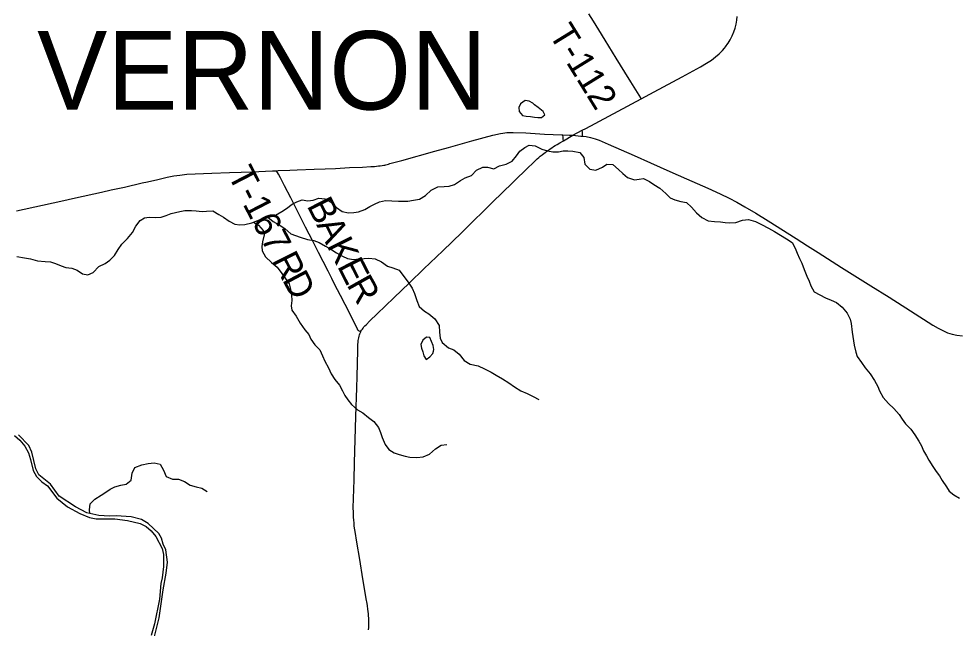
# Model space of a CAD drawing. Extents: x 1442749 to 1756758, y 235267 to 677782.
# Drawn here: x 1557967 to 1568709, y 500562 to 507542 of the extents above; entities that cross this region are included whole.
import ezdxf

# ---------------------------------------------------------------- set-up
doc = ezdxf.new("R2010")
doc.units = 0
for name, color, linetype in [('GM_X_Major_River', 7, 'Continuous'), ('GM_X_Minor_Lake', 7, 'Continuous'), ('GM_X_Minor_River', 7, 'Continuous'), ('GM_X_State_Route', 7, 'Continuous'), ('GM_X_Township_Road', 7, 'Continuous'), ('GM_X_Township_Road_Text', 7, 'Continuous'), ('GM_X_Township_Text', 7, 'Continuous')]:
    doc.layers.add(name, color=color, linetype=linetype)

msp = doc.modelspace()

# ---------------------------------------------------------------- linework, layer by layer
at = {"layer": 'GM_X_Major_River'}
for points in [[(1557917, 502769), (1557981, 502714), (1558036, 502647), (1558079, 502570), (1558103, 502496), (1558132, 502367), (1558171, 502300), (1558230, 502240), (1558297, 502191), (1558403, 502051), (1558524, 501951), (1558667, 501875), (1558778, 501829), (1558854, 501814), (1559065, 501813), (1559210, 501795), (1559356, 501761), (1559424, 501726), (1559483, 501677), (1559538, 501612), (1559610, 501475), (1559625, 501405), (1559625, 501267), (1559609, 501140), (1559592, 501075), (1559578, 500896), (1559522, 500611), (1559484, 500477)], [(1559505, 500406), (1559573, 500680), (1559619, 501000), (1559656, 501194), (1559668, 501320), (1559652, 501459), (1559621, 501525), (1559602, 501594), (1559571, 501648), (1559448, 501762), (1559371, 501807), (1559253, 501839), (1559081, 501851), (1559005, 501844), (1558885, 501854), (1558780, 501876), (1558745, 501884), (1558618, 501954), (1558430, 502074), (1558330, 502210), (1558195, 502318), (1558162, 502389), (1558117, 502578), (1558082, 502654), (1557965, 502776)]]:
    msp.add_lwpolyline(points, dxfattribs=at)
at = {"layer": 'GM_X_Minor_Lake'}
for points in [[(1563853, 506574), (1563808, 506599), (1563762, 506606), (1563711, 506569), (1563692, 506527), (1563695, 506479), (1563734, 506436), (1563776, 506426), (1563826, 506423), (1563870, 506416), (1563910, 506411), (1563929, 506411)], [(1563929, 506411), (1563952, 506410), (1563989, 506442), (1563969, 506482), (1563914, 506527), (1563869, 506556), (1563853, 506574)], [(1562592, 503862), (1562571, 503813), (1562579, 503770), (1562594, 503728), (1562605, 503680), (1562631, 503641), (1562671, 503669), (1562706, 503710), (1562713, 503734)], [(1562713, 503734), (1562718, 503754), (1562711, 503801), (1562690, 503845), (1562674, 503891), (1562634, 503896), (1562592, 503862)]]:
    msp.add_lwpolyline(points, dxfattribs=at)
at = {"layer": 'GM_X_Minor_River'}
for points in [[(1559408, 505262), (1559460, 505271), (1559532, 505267), (1559598, 505270), (1559654, 505289), (1559711, 505310), (1559811, 505336), (1559867, 505347), (1559945, 505345), (1559997, 505344), (1560067, 505335), (1560117, 505338), (1560189, 505342), (1560257, 505301), (1560310, 505268), (1560377, 505224), (1560440, 505191), (1560496, 505182), (1560554, 505185), (1560635, 505205), (1560705, 505232), (1560778, 505261), (1560905, 505294), (1560977, 505335), (1561032, 505370), (1561097, 505419), (1561152, 505446), (1561210, 505467), (1561276, 505457), (1561336, 505464), (1561403, 505489), (1561471, 505481), (1561540, 505440), (1561604, 505379), (1561670, 505335), (1561741, 505320), (1561803, 505323), (1561857, 505330), (1561930, 505358), (1561987, 505391), (1562039, 505418), (1562096, 505447), (1562164, 505462), (1562238, 505458), (1562312, 505453), (1562420, 505455), (1562486, 505465), (1562555, 505476), (1562621, 505519), (1562689, 505580), (1562765, 505618), (1562836, 505623), (1562894, 505624), (1562956, 505645), (1563025, 505689), (1563078, 505720), (1563150, 505747), (1563207, 505808), (1563280, 505842), (1563332, 505843), (1563404, 505822), (1563469, 505859), (1563545, 505877), (1563616, 505912), (1563665, 505973), (1563704, 506026), (1563759, 506069), (1563809, 506096), (1563879, 506085), (1563954, 506048), (1564018, 506028), (1564080, 506019), (1564144, 506020), (1564200, 506029), (1564252, 506028), (1564310, 506025), (1564390, 506009), (1564437, 505952), (1564447, 505878), (1564504, 505820), (1564574, 505807), (1564648, 505842), (1564699, 505877), (1564767, 505873), (1564832, 505814), (1564883, 505771), (1564934, 505726), (1565017, 505698), (1565068, 505707), (1565120, 505712), (1565187, 505679), (1565238, 505644), (1565304, 505602), (1565374, 505541), (1565425, 505490), (1565477, 505467), (1565546, 505451), (1565612, 505436), (1565667, 505385), (1565724, 505318), (1565787, 505266)], [(1557944, 504818), (1558034, 504806), (1558102, 504793), (1558183, 504771), (1558271, 504761), (1558331, 504758), (1558387, 504741), (1558452, 504712), (1558506, 504694), (1558574, 504687), (1558635, 504664), (1558698, 504621), (1558756, 504611), (1558817, 504638), (1558882, 504705), (1558955, 504740), (1559008, 504779), (1559063, 504832), (1559104, 504901), (1559147, 504962), (1559211, 505027), (1559270, 505096), (1559306, 505167), (1559357, 505231), (1559408, 505262)], [(1560654, 505213), (1560710, 505180), (1560765, 505119), (1560776, 505066), (1560758, 504987), (1560751, 504935), (1560754, 504885), (1560793, 504814), (1560859, 504750), (1560926, 504699), (1560977, 504624), (1561018, 504573), (1561064, 504508), (1561079, 504447), (1561090, 504377), (1561092, 504315), (1561085, 504255), (1561094, 504203), (1561141, 504136), (1561189, 504054)], [(1560819, 505271), (1560879, 505219), (1560946, 505183), (1561013, 505140), (1561082, 505080), (1561189, 505042), (1561273, 505015), (1561343, 505001), (1561406, 504978), (1561477, 504938), (1561539, 504905), (1561606, 504862), (1561673, 504822), (1561730, 504795), (1561800, 504784), (1561868, 504793), (1561921, 504798), (1561975, 504800), (1562048, 504791), (1562118, 504758), (1562189, 504710), (1562248, 504691), (1562320, 504663), (1562376, 504592), (1562423, 504525), (1562472, 504458), (1562496, 504394), (1562523, 504317), (1562551, 504248), (1562610, 504193), (1562662, 504162), (1562730, 504106), (1562778, 504029)], [(1565787, 505266), (1565860, 505229), (1565932, 505219), (1565998, 505216), (1566052, 505209), (1566107, 505204), (1566176, 505208), (1566250, 505237), (1566322, 505244), (1566400, 505222), (1566469, 505185), (1566548, 505143), (1566618, 505106), (1566687, 505062), (1566756, 505021), (1566819, 504979), (1566854, 504915), (1566877, 504858), (1566903, 504795), (1566930, 504743), (1566957, 504672), (1566989, 504595), (1567014, 504537), (1567035, 504482), (1567073, 504415), (1567135, 504382), (1567200, 504347), (1567268, 504321), (1567327, 504292), (1567392, 504239), (1567449, 504172), (1567485, 504103), (1567494, 504051), (1567506, 503954)], [(1561189, 504054), (1561240, 503981), (1561289, 503926), (1561309, 503874), (1561356, 503809), (1561413, 503750), (1561442, 503681), (1561471, 503619), (1561512, 503544), (1561545, 503474), (1561586, 503411), (1561639, 503344), (1561674, 503279), (1561700, 503229), (1561735, 503176), (1561774, 503126), (1561843, 503063), (1561905, 503028), (1561970, 502977), (1562030, 502930), (1562085, 502861), (1562106, 502803), (1562127, 502746), (1562160, 502666), (1562203, 502609), (1562265, 502570), (1562323, 502551), (1562392, 502532), (1562444, 502523), (1562522, 502518), (1562596, 502525), (1562669, 502556), (1562736, 502616), (1562801, 502657), (1562869, 502666)], [(1562778, 504029), (1562783, 503952), (1562790, 503884), (1562812, 503833), (1562885, 503772), (1562947, 503749), (1563010, 503700), (1563067, 503629), (1563136, 503588), (1563224, 503569), (1563298, 503532), (1563375, 503493), (1563433, 503460), (1563504, 503417), (1563576, 503372), (1563643, 503327), (1563715, 503282), (1563786, 503249), (1563856, 503216), (1563919, 503183)], [(1567506, 503954), (1567521, 503854), (1567530, 503803), (1567547, 503725), (1567564, 503675), (1567615, 503604), (1567656, 503545), (1567711, 503474), (1567764, 503401), (1567799, 503331), (1567819, 503280), (1567862, 503204), (1567923, 503135), (1567982, 503078), (1568043, 503009), (1568078, 502958), (1568117, 502901), (1568177, 502840), (1568226, 502778), (1568269, 502703), (1568300, 502650), (1568323, 502592), (1568356, 502535), (1568386, 502485), (1568431, 502414), (1568470, 502357), (1568505, 502307), (1568536, 502252), (1568585, 502181), (1568619, 502131), (1568670, 502090), (1568734, 502051)], [(1558779, 501875), (1558778, 501917), (1558785, 501986), (1558838, 502041), (1558912, 502086), (1558963, 502121), (1559015, 502153), (1559068, 502182), (1559136, 502199), (1559196, 502212), (1559255, 502258), (1559264, 502336), (1559295, 502402), (1559376, 502432), (1559448, 502448), (1559518, 502455), (1559586, 502442), (1559623, 502371), (1559654, 502300), (1559726, 502271), (1559796, 502268), (1559866, 502243), (1559931, 502200), (1559999, 502180), (1560063, 502165), (1560124, 502128)]]:
    msp.add_lwpolyline(points, dxfattribs=at)
at = {"layer": 'GM_X_State_Route'}
for points in [[(1563739, 505781), (1563800, 505841), (1563844, 505882), (1563876, 505913), (1563903, 505937), (1563920, 505953), (1563937, 505967), (1563959, 505985), (1563982, 506003), (1563999, 506015), (1564012, 506025), (1564031, 506039), (1564049, 506052), (1564068, 506064), (1564088, 506078), (1564109, 506091), (1564130, 506104), (1564162, 506122), (1564202, 506145), (1564308, 506208), (1564417, 506265), (1564457, 506286), (1565091, 506626), (1565241, 506706), (1565562, 506878), (1565770, 506991), (1565841, 507033), (1565896, 507069), (1565943, 507105), (1565985, 507142), (1566022, 507180), (1566045, 507207), (1566056, 507220), (1566085, 507260), (1566086, 507261), (1566112, 507302), (1566135, 507346), (1566154, 507392), (1566169, 507436), (1566180, 507481), (1566188, 507526), (1566192, 507569)], [(1557943, 505342), (1558449, 505455), (1558615, 505492), (1558913, 505558), (1559025, 505582), (1559176, 505615), (1559380, 505663), (1559440, 505675), (1559558, 505702), (1559664, 505727), (1559744, 505743), (1559809, 505752), (1559890, 505761), (1559988, 505766), (1560178, 505773), (1560378, 505781), (1560513, 505787), (1560634, 505790), (1560873, 505800), (1560918, 505802), (1560938, 505803), (1561069, 505808), (1561155, 505812), (1561348, 505820), (1561473, 505824), (1561594, 505829), (1561754, 505837), (1561902, 505843), (1561997, 505849), (1562039, 505851), (1562063, 505853), (1562086, 505856), (1562105, 505858), (1562126, 505861), (1562147, 505865), (1562158, 505867), (1562170, 505871), (1562183, 505874), (1562198, 505878), (1562215, 505883), (1562231, 505887), (1562246, 505891), (1562351, 505920), (1562730, 506025), (1562885, 506068), (1563046, 506113), (1563154, 506143), (1563394, 506209), (1563480, 506228), (1563507, 506233), (1563531, 506237), (1563554, 506239), (1563577, 506240), (1563597, 506241), (1563626, 506241), (1563770, 506234), (1563986, 506222), (1564183, 506213), (1564196, 506213), (1564271, 506209), (1564288, 506209), (1564308, 506208)], [(1564202, 506145), (1564200, 506166), (1564198, 506184), (1564196, 506213)], [(1564308, 506208), (1564402, 506199), (1564422, 506196), (1564461, 506192), (1564513, 506181), (1564564, 506168), (1564611, 506151), (1564713, 506107), (1565010, 505975), (1565199, 505891), (1565421, 505793), (1565610, 505709), (1565856, 505601), (1565994, 505539), (1566098, 505489), (1566188, 505442), (1566279, 505390), (1566406, 505314), (1566546, 505229), (1566867, 505024), (1566994, 504943), (1567119, 504864), (1567385, 504695), (1567720, 504483), (1567929, 504352), (1568176, 504196), (1568430, 504034), (1568492, 503997), (1568544, 503970), (1568598, 503947), (1568651, 503931), (1568705, 503919), (1568769, 503909)], [(1564422, 506196), (1564421, 506212), (1564419, 506241), (1564417, 506265)], [(1561971, 500545), (1561973, 500572), (1561975, 500595), (1561976, 500613), (1561976, 500633), (1561975, 500653), (1561974, 500679), (1561972, 500704), (1561970, 500726), (1561967, 500752), (1561963, 500782), (1561958, 500818), (1561954, 500845), (1561945, 500899), (1561936, 500947), (1561906, 501127), (1561870, 501349), (1561837, 501548), (1561818, 501670), (1561812, 501707), (1561808, 501736), (1561805, 501765), (1561801, 501805), (1561799, 501831), (1561798, 501853), (1561797, 501892), (1561796, 501940), (1561805, 502263), (1561812, 502458), (1561827, 502985), (1561835, 503315), (1561840, 503445), (1561847, 503743), (1561849, 503789), (1561850, 503815), (1561851, 503835), (1561854, 503856), (1561856, 503872), (1561858, 503888), (1561863, 503908), (1561867, 503923), (1561871, 503935), (1561877, 503950), (1561881, 503957), (1561883, 503963), (1561891, 503975), (1561900, 503988), (1561908, 503999), (1561918, 504012), (1561929, 504024), (1561942, 504038), (1561984, 504081), (1562068, 504163), (1562260, 504345), (1562440, 504517), (1562605, 504678), (1562820, 504886), (1563037, 505095), (1563181, 505235), (1563277, 505329), (1563376, 505425), (1563521, 505567), (1563603, 505648), (1563687, 505731), (1563739, 505781)]]:
    msp.add_lwpolyline(points, dxfattribs=at)
at = {"layer": 'GM_X_Township_Road'}
for points in [[(1565091, 506626), (1565086, 506635), (1564974, 506819), (1564905, 506931), (1564807, 507090), (1564678, 507296), (1564608, 507414), (1564546, 507514), (1564492, 507599)], [(1561881, 503957), (1561864, 503966), (1561856, 503970), (1561849, 503977), (1561844, 503986), (1561756, 504167), (1561650, 504372), (1561583, 504504), (1561549, 504567), (1561507, 504652), (1561450, 504762), (1561398, 504865), (1561332, 504996), (1561251, 505154), (1561166, 505323), (1561080, 505490), (1561009, 505630), (1560963, 505721), (1560941, 505761), (1560918, 505802)]]:
    msp.add_lwpolyline(points, dxfattribs=at)

# ---------------------------------------------------------------- texts
at = {"layer": 'GM_X_Township_Road_Text'}
for s, rotation, p in [('T-112', 301.6855, (1564027, 507367)), ('T-167', 297.2926, (1560353, 505759)), ('B', 296.6698, (1561259, 505403)), ('A', 296.6661, (1561370, 505183)), ('K', 296.6682, (1561488, 504947)), ('R', 296.8339, (1560864, 504780)), ('E', 296.9243, (1561607, 504710)), ('D', 297.9331, (1560978, 504555)), ('R', 299.2652, (1561715, 504498))]:
    msp.add_text(s, height=300, rotation=rotation, dxfattribs=at).set_placement(p)
at = {"layer": 'GM_X_Township_Text'}
msp.add_text('VERNON', height=900, rotation=0, dxfattribs=at).set_placement((1558178, 506502))

doc.saveas('drawing.dxf')
